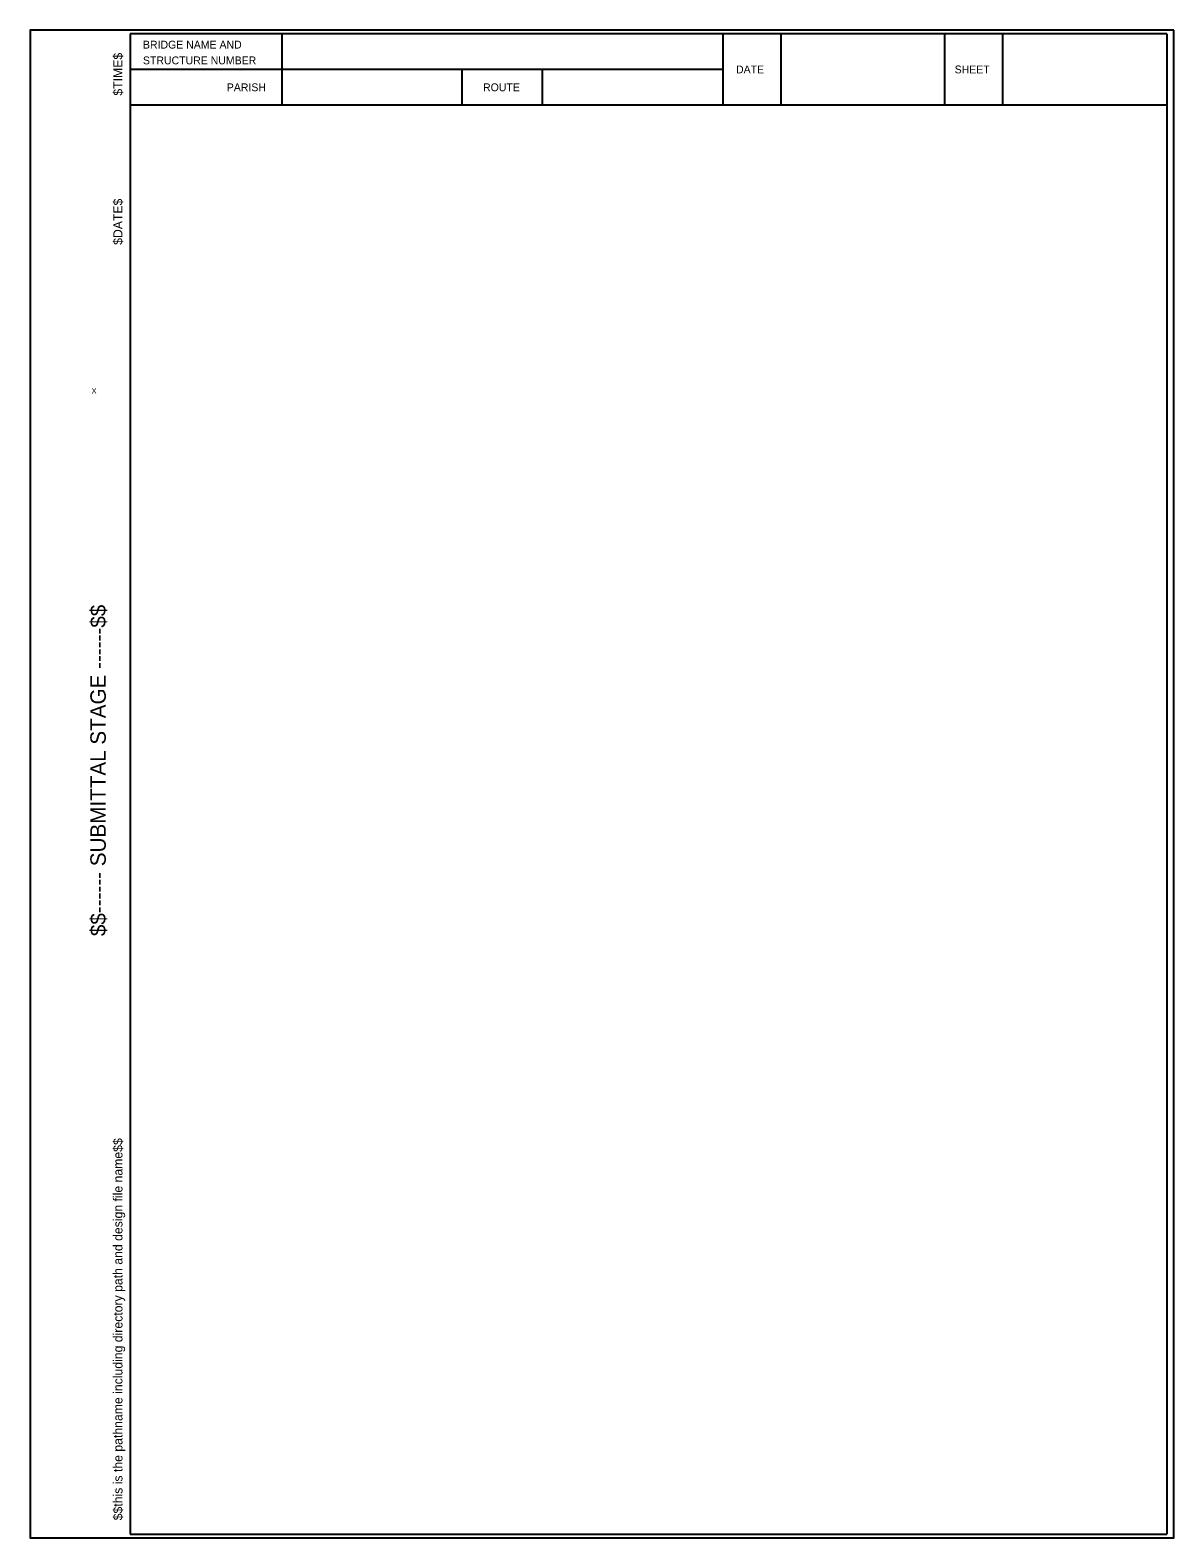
# Model space of a CAD drawing. Extents: x -1.4 to 14.6, y 0 to 21.1.
import ezdxf

# ---------------------------------------------------------------- set-up
doc = ezdxf.new("R2010")
doc.units = 0
for name, color, linetype in [('Construction Class', 7, 'Continuous'), ('Plot Border', 7, 'Continuous'), ('Sheet Border', 7, 'Continuous')]:
    doc.layers.add(name, color=color, linetype=linetype)

msp = doc.modelspace()

# ---------------------------------------------------------------- linework, layer by layer
at = {"layer": 'Construction Class'}
msp.add_line((-0.5, 16), (-0.5, 16), dxfattribs=at)
at = {"layer": 'Plot Border'}
msp.add_lwpolyline([(14.6, 21.05), (-1.4, 21.05), (-1.4, -0.05), (14.6, -0.05)], close=True, dxfattribs=at)
at = {"layer": 'Sheet Border'}
for p, q in [((14.5, 21), (0, 21)), ((0, 21), (0, 0)), ((2.119, 21), (2.119, 20)), ((8.294, 20), (8.294, 21)), ((9.104, 21), (9.104, 20)), ((11.397, 20), (11.397, 21)), ((12.207, 20), (12.207, 21)), ((14.5, 21), (14.5, 0)), ((14.5, 21), (14.5, 0)), ((8.294, 20.5), (0, 20.5)), ((4.644, 20), (4.644, 20.5)), ((5.769, 20), (5.769, 20.5)), ((14.5, 20), (0, 20)), ((0, 0), (14.5, 0))]:
    msp.add_line(p, q, dxfattribs=at)

# ---------------------------------------------------------------- texts
at = {"layer": 'Plot Border'}
for s, height, p in [('$TIME$', 0.128, (-0.109, 20.133)), ('$DATE$', 0.128, (-0.109, 18.045)), ('$$------ SUBMITTAL STAGE ------$$', 0.216, (-0.342, 8.371)), ('$$this is the pathname including directory path and design file name$$', 0.128, (-0.109, 0.195))]:
    msp.add_text(s, height=height, rotation=90, dxfattribs=at).set_placement(p)
at = {"layer": 'Sheet Border'}
for s, height, p in [('BRIDGE NAME AND', 0.11, (0.178, 20.792)), ('STRUCTURE NUMBER', 0.11, (0.178, 20.572)), ('DATE', 0.11, (8.475, 20.445)), ('SHEET', 0.11, (11.534, 20.445)), ('PARISH', 0.11, (1.351, 20.195)), ('ROUTE', 0.11, (4.936, 20.195)), ('X', 0.075, (-0.54, 15.963))]:
    msp.add_text(s, height=height, dxfattribs=at).set_placement(p)

doc.saveas('drawing.dxf')
